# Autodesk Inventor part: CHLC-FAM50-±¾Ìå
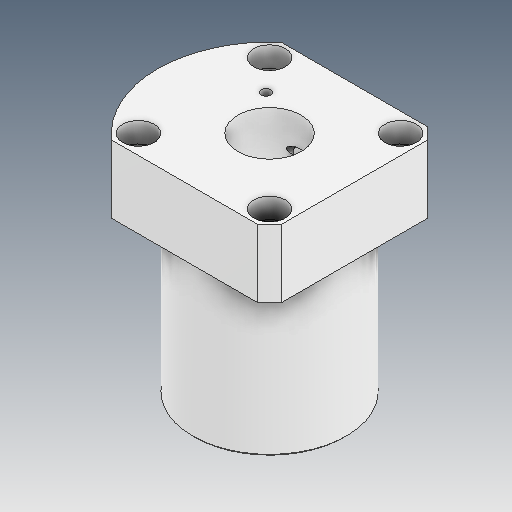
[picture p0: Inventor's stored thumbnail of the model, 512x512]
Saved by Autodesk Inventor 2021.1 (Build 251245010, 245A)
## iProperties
Created: 2021-05
Part Number: CHLC-FAM50-±¾Ìå
Material: Ogólny
Document SubType Name: Modeling
Designer: user
Density: 1 g/cm^3
Appearance: Domyślna
Author: user
Revision Number: ÈÎºÎ
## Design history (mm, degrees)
feature "NONE"
feature "Złożony1"
node "Bryła1"
body "Srf1"
